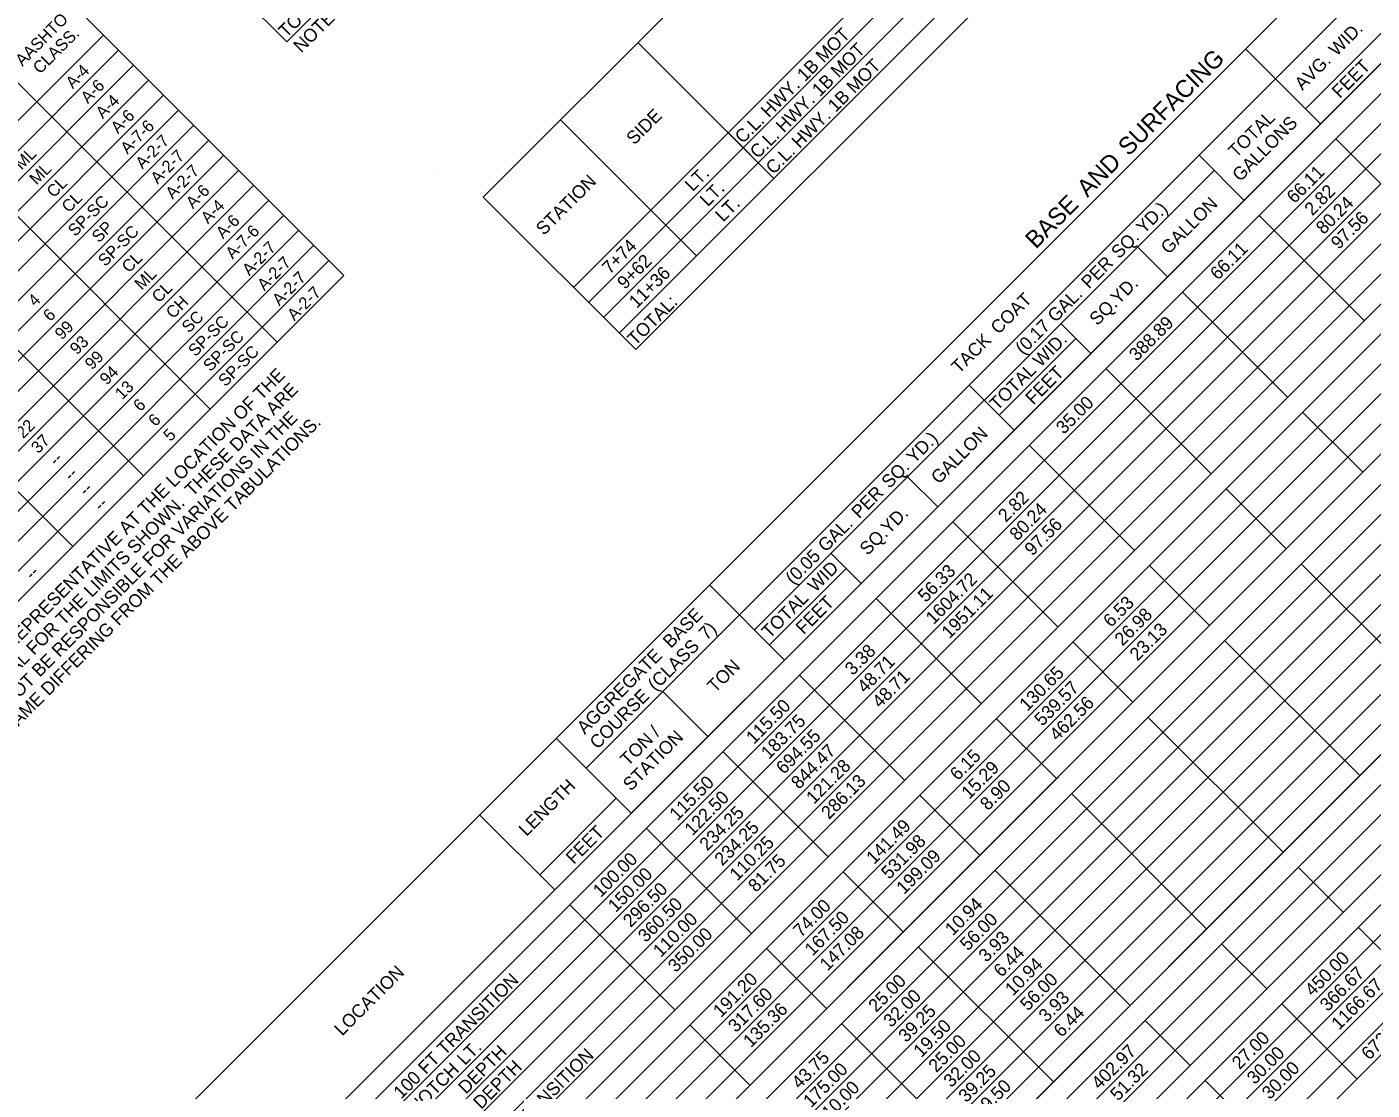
# Model space of a CAD drawing. Extents: x 1675667 to 1681231, y 227227 to 232694.
# Drawn here: x 1678522 to 1679139, y 230133 to 230621 of the extents above; entities that cross this region are included whole.
import ezdxf

# ---------------------------------------------------------------- set-up
doc = ezdxf.new("R2010")
doc.units = 0
doc.layers.add('Default', color=7, linetype='Continuous')

msp = doc.modelspace()

# ---------------------------------------------------------------- linework, layer by layer
at = {"layer": 'Default'}
for p, q in [((1678525.01, 230054.56), (1679538.35, 231068.14)), ((1678778.69, 230280.72), (1679552.14, 231054.36)), ((1678559.49, 230020.09), (1679572.82, 231033.68)), ((1678566.38, 230013.2), (1679579.72, 231026.78)), ((1678573.28, 230006.31), (1679586.61, 231019.89)), ((1678580.17, 229999.41), (1679593.51, 231013)), ((1678587.07, 229992.52), (1679600.4, 231006.1)), ((1678593.96, 229985.63), (1679607.3, 230999.21)), ((1678600.86, 229978.73), (1679614.2, 230992.32)), ((1678607.75, 229971.84), (1679621.09, 230985.42)), ((1678614.65, 229964.94), (1679627.99, 230978.53)), ((1678614.65, 229964.94), (1679627.99, 230978.53)), ((1678621.54, 229958.05), (1679634.88, 230971.64)), ((1678628.44, 229951.16), (1679641.78, 230964.74)), ((1678635.33, 229944.26), (1679648.67, 230957.85)), ((1678642.23, 229937.37), (1679655.57, 230950.96)), ((1678649.12, 229930.48), (1679662.46, 230944.06)), ((1678656.02, 229923.58), (1679669.36, 230937.17)), ((1678662.91, 229916.69), (1679676.25, 230930.28)), ((1678669.81, 229909.8), (1679683.15, 230923.38)), ((1678676.71, 229902.9), (1679690.04, 230916.49)), ((1678683.6, 229896.01), (1679696.94, 230909.6)), ((1678690.5, 229889.12), (1679703.83, 230902.7)), ((1678697.39, 229882.22), (1679710.73, 230895.81)), ((1678731.42, 230542.8), (1679082.99, 230894.46)), ((1678704.29, 229875.33), (1679717.62, 230888.92)), ((1678641.22, 230614.18), (1678911.09, 230884.12)), ((1678711.18, 229868.44), (1679724.52, 230882.02)), ((1678718.08, 229861.54), (1679731.41, 230875.13)), ((1678724.97, 229854.65), (1679738.31, 230868.24)), ((1678731.87, 229847.76), (1679745.2, 230861.34)), ((1678738.76, 229840.86), (1679752.1, 230854.45)), ((1678745.66, 229833.97), (1679758.99, 230847.55)), ((1678745.66, 229833.97), (1679758.99, 230847.55)), ((1678779.69, 230494.55), (1679131.26, 230846.2)), ((1678752.55, 229827.08), (1679765.89, 230840.66)), ((1678786.58, 230487.66), (1679138.15, 230839.31)), ((1678759.45, 229820.18), (1679772.78, 230833.77)), ((1678793.82, 230480.42), (1679145.39, 230832.07)), ((1678766.34, 229813.29), (1679779.68, 230826.87)), ((1678801.41, 230472.84), (1679152.98, 230824.49)), ((1678773.24, 229806.4), (1679786.57, 230819.98)), ((1678780.13, 229799.5), (1679793.47, 230813.09)), ((1678787.03, 229792.61), (1679800.36, 230806.19)), ((1678772.79, 230501.44), (1678989.59, 230718.3)), ((1678772.79, 230501.44), (1678954.09, 230682.79)), ((1678641.22, 230614.18), (1678579.16, 230676.22)), ((1678641.22, 230614.18), (1678579.16, 230676.22)), ((1678667.47, 230506.95), (1678527.85, 230646.54)), ((1678235.23, 230295.24), (1678557.15, 230617.25)), ((1678465.12, 230525.19), (1678557.15, 230617.25)), ((1678864.83, 230551.44), (1678802.43, 230613.82)), ((1679108.89, 230583.42), (1679144.05, 230618.59)), ((1678242.12, 230288.35), (1678564.05, 230610.35)), ((1678636.8, 230476.27), (1678505.79, 230607.24)), ((1679045.48, 230506.2), (1679150.95, 230611.7)), ((1679115.79, 230576.53), (1679081.31, 230611)), ((1678249.02, 230281.46), (1678570.94, 230603.46)), ((1678255.91, 230274.56), (1678577.84, 230596.56)), ((1678262.81, 230267.67), (1678584.73, 230589.67)), ((1678269.7, 230260.77), (1678591.63, 230582.78)), ((1678606.12, 230445.58), (1678475.11, 230576.56)), ((1678829.33, 230515.93), (1678766.93, 230578.31)), ((1678276.6, 230253.88), (1678598.52, 230575.88)), ((1678864.83, 230551.44), (1678843.8, 230572.46)), ((1678283.49, 230246.99), (1678605.42, 230568.99)), ((1679170.95, 230521.38), (1679122.68, 230569.64)), ((1679170.95, 230521.38), (1679122.68, 230569.64)), ((1678290.39, 230240.09), (1678612.31, 230562.1)), ((1679080.63, 230541.36), (1679059.95, 230562.05)), ((1678297.28, 230233.2), (1678619.21, 230555.2)), ((1678711.08, 230554.87), (1678711.08, 230554.87)), ((1678855.9, 230344.16), (1679066.84, 230555.15)), ((1678304.18, 230226.31), (1678626.1, 230548.31)), ((1678575.45, 230414.9), (1678444.44, 230545.88)), ((1678311.07, 230219.41), (1678633, 230541.42)), ((1678801.41, 230472.84), (1678731.42, 230542.8)), ((1678801.41, 230472.84), (1678731.42, 230542.8)), ((1678317.97, 230212.52), (1678639.89, 230534.52)), ((1678829.33, 230515.93), (1678808.3, 230536.95)), ((1679135.79, 230486.22), (1679087.53, 230534.47)), ((1679135.79, 230486.22), (1679087.53, 230534.47)), ((1678324.86, 230205.63), (1678646.79, 230527.63)), ((1678331.76, 230198.73), (1678653.68, 230520.74)), ((1679045.48, 230506.2), (1679031.69, 230519.99)), ((1678338.65, 230191.84), (1678660.58, 230513.84)), ((1678345.55, 230184.95), (1678667.47, 230506.95)), ((1678543.05, 230382.49), (1678418.93, 230506.57)), ((1679010.32, 230471.03), (1679045.48, 230506.2)), ((1679100.64, 230451.05), (1679052.37, 230499.31)), ((1679100.64, 230451.05), (1679052.37, 230499.31)), ((1679010.32, 230471.03), (1678996.53, 230484.82)), ((1678968.27, 230442.76), (1679003.42, 230477.93)), ((1679010.32, 230471.03), (1679003.42, 230477.93)), ((1678904.85, 230365.54), (1679010.32, 230471.03)), ((1679065.48, 230415.89), (1679017.21, 230464.14)), ((1679065.48, 230415.89), (1679017.21, 230464.14)), ((1678975.16, 230435.87), (1678954.48, 230456.55)), ((1678959.33, 230240.76), (1679170.27, 230451.75)), ((1679135.11, 230416.58), (1679107.53, 230444.16)), ((1679135.11, 230416.58), (1679107.53, 230444.16)), ((1679030.32, 230380.72), (1678982.06, 230428.98)), ((1679030.32, 230380.72), (1678982.06, 230428.98)), ((1678940.01, 230400.7), (1678926.22, 230414.49)), ((1679099.96, 230381.42), (1679072.38, 230408.99)), ((1679099.96, 230381.42), (1679072.38, 230408.99)), ((1678995.17, 230345.56), (1678946.9, 230393.81)), ((1678995.17, 230345.56), (1678946.9, 230393.81)), ((1678904.85, 230365.54), (1678891.06, 230379.33)), ((1679064.8, 230346.25), (1679037.22, 230373.83)), ((1679064.8, 230346.25), (1679037.22, 230373.83)), ((1679168.91, 230312.49), (1679106.85, 230374.53)), ((1679168.91, 230312.49), (1679106.85, 230374.53)), ((1678862.8, 230337.27), (1678897.95, 230372.43)), ((1678904.85, 230365.54), (1678897.95, 230372.43)), ((1678799.38, 230260.04), (1678904.85, 230365.54)), ((1678869.69, 230330.37), (1678835.22, 230364.84)), ((1678960.01, 230310.39), (1678911.74, 230358.65)), ((1678960.01, 230310.39), (1678911.74, 230358.65)), ((1679029.64, 230311.09), (1679002.06, 230338.66)), ((1679029.64, 230311.09), (1679002.06, 230338.66)), ((1679133.75, 230277.32), (1679071.69, 230339.36)), ((1679133.75, 230277.32), (1679071.69, 230339.36)), ((1678924.85, 230275.23), (1678876.59, 230323.48)), ((1678924.85, 230275.23), (1678876.59, 230323.48)), ((1678834.54, 230295.21), (1678813.85, 230315.89)), ((1679133.75, 230277.32), (1679168.91, 230312.49)), ((1678994.49, 230275.92), (1678966.91, 230303.5)), ((1678994.49, 230275.92), (1678966.91, 230303.5)), ((1679098.59, 230242.15), (1679036.54, 230304.2)), ((1679098.59, 230242.15), (1679036.54, 230304.2)), ((1678799.38, 230260.04), (1678764.9, 230294.51)), ((1678889.7, 230240.06), (1678841.43, 230288.32)), ((1678889.7, 230240.06), (1678841.43, 230288.32)), ((1679063.44, 230206.99), (1679133.75, 230277.32)), ((1678959.33, 230240.76), (1678931.75, 230268.33)), ((1678959.33, 230240.76), (1678931.75, 230268.33)), ((1679063.44, 230206.99), (1679001.38, 230269.03)), ((1679063.44, 230206.99), (1679001.38, 230269.03)), ((1678757.33, 230231.77), (1678792.48, 230266.94)), ((1678799.38, 230260.04), (1678792.48, 230266.94)), ((1678764.22, 230224.88), (1678729.75, 230259.35)), ((1678854.54, 230204.9), (1678806.27, 230253.15)), ((1678854.54, 230204.9), (1678806.27, 230253.15)), ((1678649.12, 229930.48), (1678959.33, 230240.76)), ((1678924.17, 230205.59), (1678896.59, 230233.17)), ((1678924.17, 230205.59), (1678896.59, 230233.17)), ((1679028.28, 230171.82), (1678966.22, 230233.87)), ((1679028.28, 230171.82), (1678966.22, 230233.87)), ((1679126.17, 230214.58), (1679105.49, 230235.26)), ((1679126.17, 230214.58), (1679105.49, 230235.26)), ((1678819.38, 230169.73), (1678771.12, 230217.98)), ((1678819.38, 230169.73), (1678771.12, 230217.98)), ((1679028.28, 230171.82), (1679063.44, 230206.99)), ((1679167.55, 230173.22), (1679133.07, 230207.69)), ((1679167.55, 230173.22), (1679133.07, 230207.69)), ((1679091.02, 230179.42), (1679070.33, 230200.1)), ((1679091.02, 230179.42), (1679070.33, 230200.1)), ((1678889.02, 230170.43), (1678861.44, 230198)), ((1678889.02, 230170.43), (1678861.44, 230198)), ((1678993.12, 230136.66), (1678931.07, 230198.7)), ((1678993.12, 230136.66), (1678931.07, 230198.7)), ((1678993.12, 230136.66), (1679028.28, 230171.82)), ((1679132.39, 230138.06), (1679097.91, 230172.52)), ((1679132.39, 230138.06), (1679097.91, 230172.52)), ((1678853.86, 230135.26), (1678826.28, 230162.84)), ((1678853.86, 230135.26), (1678826.28, 230162.84)), ((1678957.97, 230101.49), (1678895.91, 230163.54)), ((1678957.97, 230101.49), (1678895.91, 230163.54)), ((1679055.86, 230144.25), (1679035.18, 230164.93)), ((1679055.86, 230144.25), (1679035.18, 230164.93)), ((1678957.97, 230101.49), (1678993.12, 230136.66)), ((1679097.23, 230102.89), (1679062.76, 230137.36)), ((1679097.23, 230102.89), (1679062.76, 230137.36))]:
    msp.add_line(p, q, dxfattribs=at)

# ---------------------------------------------------------------- texts
for s, height, p in [('TOTAL:', 6, (1678641.06, 230615.72)), ('AASHTO', 5.5, (1678519.93, 230602.65)), ('NOTE:', 6, (1678647.95, 230608.82)), (' MOT', 6, (1678886.06, 230602.65)), (' WID.', 6, (1679121.54, 230605.62)), ('CLASS.', 5.5, (1678528.03, 230599.08)), (' MOT', 6, (1678892.96, 230595.75)), (' SURFACING', 8, (1679025.58, 230559.25)), ('A-4', 5.5, (1678543.03, 230592.34)), (' 1B', 6, (1678877.49, 230594.07)), (' MOT', 6, (1678900.2, 230588.52)), ('AVG.', 6, (1679107.45, 230591.53)), ('FEET', 6, (1679124.53, 230587.92)), ('A-6', 5.5, (1678549.96, 230585.48)), (' HWY.', 6, (1678860.88, 230577.46)), (' 1B', 6, (1678884.38, 230587.17)), ('A-4', 5.5, (1678556.82, 230578.55)), (' HWY.', 6, (1678867.78, 230570.57)), (' 1B', 6, (1678891.62, 230579.94)), ('A-6', 5.5, (1678563.75, 230571.69)), ('SIDE', 6, (1678800.71, 230566.5)), ('A-7-6', 5.5, (1678568.15, 230562.3)), ('C.L.', 6, (1678850.53, 230567.11)), (' HWY.', 6, (1678875.02, 230563.33)), ('TOTAL', 6, (1679077.02, 230560.56)), ('GALLONS', 6, (1679078.83, 230549.64)), ('A-2-7', 5.5, (1678575.07, 230555.43)), ('C.L.', 6, (1678857.43, 230560.21)), ('ML', 5.5, (1678519.54, 230555.05)), ('A-2-7', 5.5, (1678581.96, 230548.54)), ('A-2-7', 5.5, (1678588.86, 230541.64)), ('C.L.', 6, (1678864.67, 230552.98)), (' AND', 8, (1679006.65, 230540.32)), ('ML', 5.5, (1678526.44, 230548.16)), ('STATION', 6, (1678759.21, 230524.98)), ('LT.', 6, (1678827.59, 230545.12)), ('66.11', 6, (1679103.81, 230539.62)), ('CL', 5.5, (1678534.32, 230542.25)), ('A-6', 5.5, (1678598.22, 230537.22)), ('LT.', 6, (1678834.49, 230538.22)), ('2.82', 6, (1679111.96, 230533.98)), ('CL', 5.5, (1678541.21, 230535.36)), ('SP-SC', 5.5, (1678544.12, 230524.47)), ('A-4', 5.5, (1678605.09, 230530.3)), ('LT.', 6, (1678841.56, 230531.16)), ('BASE', 8, (1678985.09, 230518.74)), (' YD.)', 6, (1679033.13, 230524.09)), ('GALLON', 6, (1679046.01, 230516.28)), ('80.24', 6, (1679117.2, 230525.43)), ('A-6', 5.5, (1678612.01, 230523.43)), ('97.56', 6, (1679124.08, 230518.53)), ('SP', 5.5, (1678555.05, 230521.61)), ('SP-SC', 5.5, (1678557.91, 230510.69)), ('A-7-6', 5.5, (1678616.42, 230514.05)), ('A-2-7', 5.5, (1678624.06, 230506.45)), ('7+74', 6, (1678789.59, 230507.1)), (' SQ.', 6, (1679021.68, 230512.63)), ('66.11', 6, (1679068.65, 230504.45)), ('CL', 5.5, (1678568.8, 230507.79)), ('A-2-7', 5.5, (1678630.95, 230499.56)), ('9+62', 6, (1678796.49, 230500.22)), (' PER', 6, (1679007.88, 230498.82)), ('ML', 5.5, (1678574.7, 230499.91)), ('A-2-7', 5.5, (1678637.85, 230492.67)), ('11+36', 6, (1678801.89, 230491.48)), ('CL', 5.5, (1678582.59, 230494)), ('SQ.YD.', 6, (1679013.28, 230483.54)), ('4', 5.5, (1678525.76, 230492.32)), ('CH', 5.5, (1678589.09, 230486.71)), ('A-2-7', 5.5, (1678644.74, 230485.77)), ('TOTAL:', 6, (1678801.25, 230474.37)), (' COAT', 6, (1678966.35, 230477.97)), (' GAL.', 6, (1678992.48, 230483.42)), ('6', 5.5, (1678532.69, 230485.46)), ('SC', 5.5, (1678596.31, 230480.15)), ('99', 5.5, (1678538.07, 230477.05)), ('SP-SC', 5.5, (1678599.28, 230469.33)), ('(0.17', 6, (1678979.24, 230470.18)), ('388.89', 6, (1679031.43, 230467.22)), ('93', 5.5, (1678544.99, 230470.19)), ('SP-SC', 5.5, (1678606.18, 230462.43)), ('TACK', 6, (1678949.9, 230461.51)), ('TOTAL WID.', 6, (1678967.44, 230444.59)), ('99', 5.5, (1678551.86, 230463.26)), ('SP-SC', 5.5, (1678613.07, 230455.54)), ('94', 5.5, (1678558.68, 230456.3)), ('FEET', 6, (1678983.9, 230447.26)), ('NOTE:  SOIL CHARACTERISTICS TABULATED ABOVE ARE REPRESENTATIVE AT THE LOCATION OF THE', 6, (1678355.62, 230175.36)), ('SAMPLE, AND FROM SURFACE INDICATIONS ARE TYPICAL FOR THE LIMITS SHOWN.  THESE DATA ARE ', 6, (1678361.99, 230169)), ('13', 5.5, (1678565.68, 230449.51)), ('6', 5.5, (1678574.06, 230444.1)), ('35.00', 6, (1678997.93, 230433.72)), ('SHOWN FOR INFORMATION ONLY.  THE STATE WILL NOT BE RESPONSIBLE FOR VARIATIONS IN THE ', 6, (1678368.35, 230162.64)), ('SOIL CHARACTERISTICS AND/OR EXTENT OF THE SAME DIFFERING FROM THE ABOVE TABULATIONS.', 6, (1678374.72, 230156.27)), ('22', 5.5, (1678520.33, 230431.73)), ('6', 5.5, (1678580.95, 230437.21)), ('5', 5.5, (1678587.91, 230430.37)), (' YD.)', 6, (1678927.7, 230418.63)), ('GALLON', 6, (1678940.54, 230410.78)), ('37', 5.5, (1678527.2, 230424.81)), ('--', 5.5, (1678535.28, 230419.1)), ('--', 5.5, (1678542.18, 230412.21)), (' SQ.', 6, (1678916.25, 230407.18)), ('--', 5.5, (1678549.07, 230405.32)), (' PER', 6, (1678902.45, 230393.37)), ('2.82', 6, (1678971.34, 230393.32)), ('--', 5.5, (1678555.97, 230398.42)), ('SQ.YD.', 6, (1678907.81, 230378.05)), ('80.24', 6, (1678976.57, 230384.77)), (' GAL.', 6, (1678887.05, 230377.97)), ('97.56', 6, (1678983.46, 230377.87)), ('(0.05', 6, (1678873.73, 230364.64)), (' WID', 6, (1678882.4, 230359.53)), ('56.33', 6, (1678934.51, 230356.49)), ('--', 5.5, (1678524.43, 230366.88)), ('1604.72', 6, (1678938.13, 230346.32)), ('TOTAL', 6, (1678862.83, 230339.95)), ('FEET', 6, (1678878.43, 230341.77)), ('1951.11', 6, (1678945.42, 230339.82)), (' BASE', 6, (1678815.94, 230333.89)), ('6.53', 6, (1679019.58, 230345.05)), ('26.98', 6, (1679024.82, 230336.5)), (' 7)', 6, (1678832.38, 230337.6)), ('23.13', 6, (1679031.72, 230329.61)), ('AGGREGATE', 6, (1678778.03, 230295.97)), (' (CLASS', 6, (1678808.96, 230314.18)), ('3.38', 6, (1678901, 230322.97)), ('TON', 6, (1678837.87, 230314.99)), ('48.71', 6, (1678906.66, 230314.84)), ('48.71', 6, (1678913.55, 230307.95)), ('130.65', 6, (1678981.11, 230306.57)), ('COURSE', 6, (1678783.89, 230289.1)), ('539.57', 6, (1678988.02, 230299.69)), ('115.50', 6, (1678855.66, 230291.41)), ('462.56', 6, (1678994.92, 230292.8)), ('183.75', 6, (1678862.53, 230284.49)), (' /', 6, (1678809.92, 230293.4)), ('694.55', 6, (1678869.43, 230277.6)), ('TON', 6, (1678797.89, 230281.36)), ('STATION', 6, (1678799.15, 230269.89)), ('844.47', 6, (1678876.34, 230270.72)), ('6.15', 6, (1678949.25, 230274.7)), ('121.28', 6, (1678883.23, 230263.83)), ('15.29', 6, (1678954.51, 230266.17)), ('LENGTH', 6, (1678751.28, 230249.06)), ('115.50', 6, (1678820.5, 230256.24)), ('286.13', 6, (1678890.13, 230256.93)), ('8.90', 6, (1678963.06, 230260.94)), ('122.50', 6, (1678827.4, 230249.35)), ('234.25', 6, (1678834.27, 230242.43)), ('234.25', 6, (1678841.17, 230235.54)), ('141.49', 6, (1678910.81, 230236.25)), ('FEET', 6, (1678772.96, 230236.27)), ('110.25', 6, (1678848.06, 230228.65)), ('531.98', 6, (1678917.71, 230229.36)), ('199.09', 6, (1678924.6, 230222.46)), ('100.00', 6, (1678785.35, 230221.08)), ('81.75', 6, (1678856.6, 230223.4)), ('150.00', 6, (1678792.24, 230214.19)), ('296.50', 6, (1678799.14, 230207.29)), ('360.50', 6, (1678806.03, 230200.4)), ('74.00', 6, (1678877.31, 230202.75)), ('10.94', 6, (1678946.95, 230203.44)), ('110.00', 6, (1678812.93, 230193.51)), ('167.50', 6, (1678882.56, 230194.2)), ('56.00', 6, (1678953.84, 230196.55)), ('350.00', 6, (1678819.82, 230186.61)), ('147.08', 6, (1678889.44, 230187.3)), ('3.93', 6, (1678962.38, 230191.3)), ('6.44', 6, (1678969.28, 230184.41)), ('10.94', 6, (1678974.53, 230175.87)), ('450.00', 6, (1679112.14, 230175.62)), ('LOCATION', 6, (1678666.66, 230157.52)), ('366.67', 6, (1679119.03, 230168.72)), (' TRANSITION', 6, (1678712.26, 230147.02)), ('191.20', 6, (1678840.51, 230165.93)), ('25.00', 6, (1678911.79, 230168.28)), ('56.00', 6, (1678981.42, 230168.98)), ('1166.67', 6, (1679124.28, 230160.17)), ('317.60', 6, (1678847.4, 230159.04)), ('32.00', 6, (1678918.68, 230161.38)), ('3.93', 6, (1678989.96, 230163.72)), ('135.36', 6, (1678854.29, 230152.14)), ('39.25', 6, (1678925.55, 230154.47)), ('6.44', 6, (1678996.86, 230156.84)), ('6728.28', 6, (1679138.07, 230146.39)), ('19.50', 6, (1678932.47, 230147.6)), ('25.00', 6, (1678939.37, 230140.7)), ('27.00', 6, (1679078.63, 230142.1)), (' FT', 6, (1678703.49, 230138.25)), (' LT.', 6, (1678721.39, 230142.36)), (' DEPTH', 6, (1678721.97, 230129.15)), (' TRANSITION', 6, (1678746.74, 230112.55)), ('43.75', 6, (1678876.61, 230133.09)), ('32.00', 6, (1678946.26, 230133.81)), ('402.97', 6, (1679014.24, 230132.85)), ('30.00', 6, (1679085.53, 230135.21)), (' NOTCH', 6, (1678699.14, 230120.11)), (' DEPTH', 6, (1678728.86, 230122.25)), ('175.00', 6, (1678881.88, 230124.57)), ('39.25', 6, (1678953.14, 230126.89)), ('51.32', 6, (1679022.81, 230127.63)), ('30.00', 6, (1679092.42, 230128.31)), (' 100', 6, (1678692.25, 230127)), ('10.00', 6, (1678890.42, 230119.33)), ('19.50', 6, (1678960.05, 230120.02))]:
    msp.add_text(s, height=height, rotation=45.00703, dxfattribs=at).set_placement(p)

doc.saveas('drawing.dxf')
